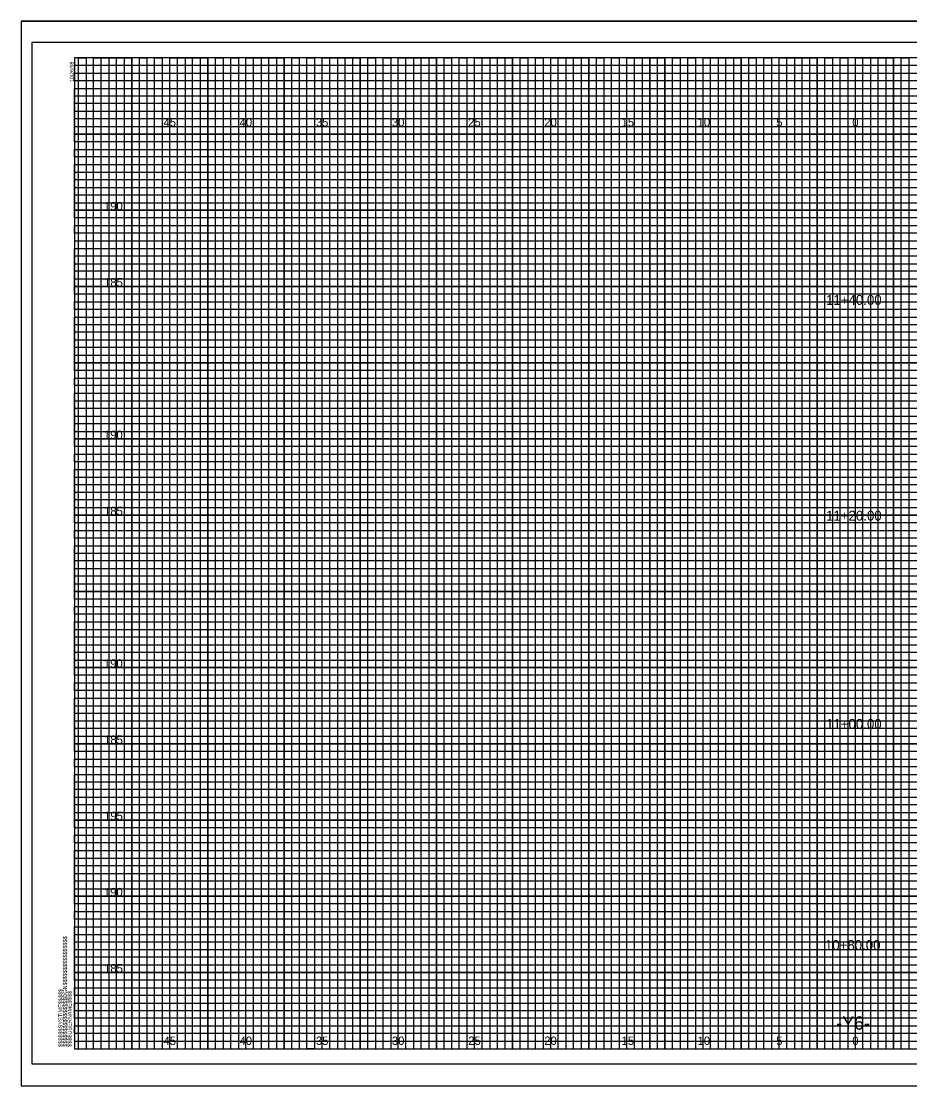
# Model space of a CAD drawing. Extents: x -4 to 103, y -2 to 138.
# Drawn here: x -3.5 to 54.8, y 68.4 to 138.2 of the extents above; entities that cross this region are included whole.
import ezdxf

# ---------------------------------------------------------------- set-up
doc = ezdxf.new("R2010")
doc.units = 0
for name, color, linetype in [('Old_Level_10', 7, 'Continuous'), ('Old_Level_16', 7, 'Continuous'), ('Old_Level_3', 7, 'Continuous'), ('Old_Level_4', 7, 'Continuous'), ('Old_Level_5', 7, 'Continuous'), ('Old_Level_8', 7, 'Continuous'), ('Prop Dimension', 7, 'Continuous'), ('Prop XS Dump Level', 7, 'Continuous'), ('Prop XS Finish Grade', 7, 'Continuous'), ('Prop XS SE Text', 7, 'Continuous'), ('Prop XS Subgrade Earthwork', 7, 'Continuous')]:
    doc.layers.add(name, color=color, linetype=linetype)

msp = doc.modelspace()

# ---------------------------------------------------------------- linework, layer by layer
at = {"layer": 'Old_Level_10'}
for p, q in [((1.25, 70.825), (1.25, 135.825)), ((3.75, 70.825), (3.75, 135.825)), ((6.25, 70.825), (6.25, 135.825)), ((8.75, 70.825), (8.75, 135.825)), ((11.25, 70.825), (11.25, 135.825)), ((13.75, 70.825), (13.75, 135.825)), ((16.25, 70.825), (16.25, 135.825)), ((18.75, 70.825), (18.75, 135.825)), ((21.25, 70.825), (21.25, 135.825)), ((23.75, 70.825), (23.75, 135.825)), ((26.25, 70.825), (26.25, 135.825)), ((28.75, 70.825), (28.75, 135.825)), ((31.25, 70.825), (31.25, 135.825)), ((33.75, 70.825), (33.75, 135.825)), ((36.25, 70.825), (36.25, 135.825)), ((38.75, 70.825), (38.75, 135.825)), ((41.25, 70.825), (41.25, 135.825)), ((43.75, 70.825), (43.75, 135.825)), ((46.25, 70.825), (46.25, 135.825)), ((48.75, 70.825), (48.75, 135.825)), ((51.25, 70.825), (51.25, 135.825)), ((53.75, 70.825), (53.75, 135.825)), ((0, 133.325), (74.25, 133.325)), ((0, 130.825), (102.5, 130.825)), ((0, 128.325), (102.5, 128.325)), ((0, 125.825), (102.5, 125.825)), ((0, 123.325), (102.5, 123.325)), ((0, 120.825), (102.5, 120.825)), ((0, 118.325), (102.5, 118.325)), ((0, 115.825), (102.5, 115.825)), ((0, 113.325), (102.5, 113.325)), ((0, 110.825), (102.5, 110.825)), ((0, 108.325), (102.5, 108.325)), ((0, 105.825), (102.5, 105.825)), ((0, 103.325), (102.5, 103.325)), ((0, 100.825), (102.5, 100.825)), ((0, 98.325), (102.5, 98.325)), ((0, 95.825), (102.5, 95.825)), ((0, 93.325), (102.5, 93.325)), ((0, 90.825), (102.5, 90.825)), ((0, 88.325), (102.5, 88.325)), ((0, 85.825), (102.5, 85.825)), ((0, 83.325), (102.5, 83.325)), ((0, 80.825), (102.5, 80.825)), ((0, 78.325), (102.5, 78.325)), ((0, 75.825), (102.5, 75.825)), ((0, 73.325), (102.5, 73.325))]:
    msp.add_line(p, q, dxfattribs=at)
at = {"layer": 'Old_Level_3'}
for p, q in [((-3.5, 138.225), (103.4, 138.225)), ((-3.5, 138.225), (-3.5, 68.4)), ((-3.5, 68.4), (102.1625, 68.4))]:
    msp.add_line(p, q, dxfattribs=at)
at = {"layer": 'Old_Level_4'}
msp.add_lwpolyline([(103, 136.825), (-2.8, 136.825), (-2.8, 69.825), (103, 69.825)], close=True, dxfattribs=at)
at = {"layer": 'Old_Level_5'}
msp.add_lwpolyline([(103.4, 138.225), (-3.5, 138.225), (-3.5, 68.4), (103.4, 68.4)], close=True, dxfattribs=at)
at = {"layer": 'Old_Level_8'}
for points in [[(1.25, 70.825), (1.25, 135.825), (3.75, 135.825), (3.75, 70.825), (6.25, 70.825), (6.25, 135.825), (8.75, 135.825), (8.75, 70.825), (11.25, 70.825), (11.25, 135.825), (13.75, 135.825), (13.75, 70.825), (16.25, 70.825), (16.25, 135.825), (18.75, 135.825), (18.75, 70.825), (21.25, 70.825), (21.25, 135.825), (23.75, 135.825), (23.75, 70.825), (26.25, 70.825), (26.25, 135.825), (28.75, 135.825), (28.75, 70.825), (31.25, 70.825), (31.25, 135.825), (33.75, 135.825), (33.75, 70.825), (36.25, 70.825), (36.25, 135.825), (38.75, 135.825), (38.75, 70.825), (41.25, 70.825), (41.25, 135.825), (43.75, 135.825), (43.75, 70.825), (46.25, 70.825), (46.25, 135.825), (48.75, 135.825), (48.75, 70.825), (51.25, 70.825), (51.25, 135.825), (53.75, 135.825), (53.75, 70.825)], [(102.5, 130.825), (0, 130.825), (0, 133.325), (74.25, 133.325)], [(102.5, 125.825), (0, 125.825), (0, 128.325), (102.5, 128.325)], [(102.5, 120.825), (0, 120.825), (0, 123.325), (102.5, 123.325)], [(102.5, 115.825), (0, 115.825), (0, 118.325), (102.5, 118.325)], [(102.5, 110.825), (0, 110.825), (0, 113.325), (102.5, 113.325)], [(102.5, 105.825), (0, 105.825), (0, 108.325), (102.5, 108.325)], [(102.5, 100.825), (0, 100.825), (0, 103.325), (102.5, 103.325)], [(102.5, 95.825), (0, 95.825), (0, 98.325), (102.5, 98.325)], [(102.5, 90.825), (0, 90.825), (0, 93.325), (102.5, 93.325)], [(102.5, 85.825), (0, 85.825), (0, 88.325), (102.5, 88.325)], [(102.5, 80.825), (0, 80.825), (0, 83.325), (102.5, 83.325)], [(102.5, 75.825), (0, 75.825), (0, 78.325), (102.5, 78.325)], [(0, 73.325), (102.5, 73.325)]]:
    msp.add_lwpolyline(points, dxfattribs=at)
at = {"layer": 'Prop Dimension'}
for points in [[(0.25, 70.825), (0.25, 135.825), (0.75, 135.825), (0.75, 70.825), (1.75, 70.825), (1.75, 135.825), (2.25, 135.825), (2.25, 70.825), (2.75, 70.825), (2.75, 135.825), (3.25, 135.825), (3.25, 70.825), (4.25, 70.825), (4.25, 135.825), (4.75, 135.825), (4.75, 70.825), (5.25, 70.825), (5.25, 135.825), (5.75, 135.825), (5.75, 70.825), (6.75, 70.825), (6.75, 135.825), (7.25, 135.825), (7.25, 70.825), (7.75, 70.825), (7.75, 135.825), (8.25, 135.825), (8.25, 70.825), (9.25, 70.825), (9.25, 135.825), (9.75, 135.825), (9.75, 70.825), (10.25, 70.825), (10.25, 135.825), (10.75, 135.825), (10.75, 70.825), (11.75, 70.825), (11.75, 135.825), (12.25, 135.825), (12.25, 70.825), (12.75, 70.825), (12.75, 135.825), (13.25, 135.825), (13.25, 70.825), (14.25, 70.825), (14.25, 135.825), (14.75, 135.825), (14.75, 70.825), (15.75, 70.825), (15.25, 70.825), (15.25, 135.825), (15.75, 135.825), (15.75, 70.825), (16.75, 70.825), (16.75, 135.825), (17.25, 135.825), (17.25, 70.825), (17.75, 70.825), (17.75, 135.825), (18.25, 135.825), (18.25, 70.825), (19.25, 70.825), (19.25, 135.825), (19.75, 135.825), (19.75, 70.825), (20.25, 70.825), (20.25, 135.825), (20.75, 135.825), (20.75, 70.825), (21.75, 70.825), (21.75, 135.825), (22.25, 135.825), (22.25, 70.825), (22.75, 70.825), (22.75, 135.825), (23.25, 135.825), (23.25, 70.825), (24.25, 70.825), (24.25, 135.825), (24.75, 135.825), (24.75, 70.825), (25.25, 70.825), (25.25, 135.825), (25.75, 135.825), (25.75, 70.825), (26.75, 70.825), (26.75, 135.825), (27.25, 135.825), (27.25, 70.825), (27.75, 70.825), (27.75, 135.825), (28.25, 135.825), (28.25, 70.825), (29.25, 70.825), (29.25, 135.825), (29.75, 135.825), (29.75, 70.825), (30.25, 70.825), (30.25, 135.825), (30.75, 135.825), (30.75, 70.825)], [(30.75, 70.825), (31.75, 70.825), (31.75, 135.825), (32.25, 135.825), (32.25, 70.825), (32.75, 70.825), (32.75, 135.825), (33.25, 135.825), (33.25, 70.825), (34.25, 70.825), (34.25, 135.825), (34.75, 135.825), (34.75, 70.825), (35.25, 70.825), (35.25, 135.825), (35.75, 135.825), (35.75, 70.825), (36.75, 70.825), (36.75, 135.825), (37.25, 135.825), (37.25, 70.825), (37.75, 70.825), (37.75, 135.825), (37.75, 70.825)], [(38.25, 135.825), (38.25, 70.825), (39.25, 70.825), (39.25, 135.825), (39.75, 135.825), (39.75, 70.825), (40.25, 70.825), (40.25, 135.825), (40.75, 135.825), (40.75, 70.825), (41.75, 70.825), (41.75, 135.825), (42.25, 135.825), (42.25, 70.825), (42.75, 70.825), (42.75, 135.825), (43.25, 135.825), (43.25, 70.825), (43.75, 70.825), (44.25, 70.825), (44.25, 135.825), (44.75, 135.825), (44.75, 70.825), (45.25, 70.825), (45.25, 135.825), (45.75, 135.825), (45.75, 70.825), (46.75, 70.825), (46.75, 135.825), (47.25, 135.825), (47.25, 70.825), (47.75, 70.825), (47.75, 135.825), (48.25, 135.825), (48.25, 70.825), (49.25, 70.825), (49.25, 135.825), (49.75, 135.825), (49.75, 70.825), (50.25, 70.825), (50.25, 135.825), (50.75, 135.825), (50.75, 70.825), (51.75, 70.825), (51.75, 135.825), (52.25, 135.825), (52.25, 70.825), (52.75, 70.825), (52.75, 135.825), (53.25, 135.825), (53.25, 70.825), (54.25, 70.825), (54.25, 135.825), (54.75, 135.825), (54.75, 70.825), (55.25, 70.825)], [(0, 132.825), (0, 133.825), (74.25, 133.825), (74.25, 134.325), (0, 134.325), (0, 134.825), (74.25, 134.825), (74.25, 135.325), (0, 135.325)], [(102.5, 132.825), (0, 132.825)], [(102.5, 131.825), (0, 131.825), (0, 132.325), (102.5, 132.325)], [(102.5, 130.325), (0, 130.325), (0, 131.325), (102.5, 131.325)], [(102.5, 129.325), (0, 129.325), (0, 129.825), (102.5, 129.825)], [(102.5, 127.825), (0, 127.825), (0, 128.825), (102.5, 128.825)], [(102.5, 126.825), (0, 126.825), (0, 127.325), (102.5, 127.325)], [(102.5, 125.325), (0, 125.325), (0, 126.325), (102.5, 126.325)], [(102.5, 124.325), (0, 124.325), (0, 124.825), (102.5, 124.825)], [(0, 123.825), (102.5, 123.825)], [(102.5, 122.825), (0, 122.825)], [(102.5, 121.825), (0, 121.825), (0, 122.325), (102.5, 122.325)], [(102.5, 120.325), (0, 120.325), (0, 121.325), (102.5, 121.325)], [(102.5, 119.325), (0, 119.325), (0, 119.825), (102.5, 119.825)], [(102.5, 117.825), (0, 117.825), (0, 118.825), (102.5, 118.825)], [(102.5, 116.825), (0, 116.825), (0, 117.325), (102.5, 117.325)], [(102.5, 115.325), (0, 115.325), (0, 116.325), (102.5, 116.325)], [(102.5, 114.325), (0, 114.325), (0, 114.825), (102.5, 114.825)], [(102.5, 112.825), (0, 112.825), (0, 113.825), (102.5, 113.825)], [(102.5, 111.825), (0, 111.825), (0, 112.325), (102.5, 112.325)], [(102.5, 110.325), (0, 110.325), (0, 111.325), (102.5, 111.325)], [(102.5, 109.325), (0, 109.325), (0, 109.825), (102.5, 109.825)], [(102.5, 107.825), (0, 107.825), (0, 108.825), (102.5, 108.825)], [(102.5, 106.825), (0, 106.825), (0, 107.325), (102.5, 107.325)], [(102.5, 105.325), (0, 105.325), (0, 106.325), (102.5, 106.325)], [(102.5, 104.325), (0, 104.325), (0, 104.825), (102.5, 104.825)], [(102.5, 102.825), (0, 102.825), (0, 103.825), (102.5, 103.825)], [(102.5, 101.825), (0, 101.825), (0, 102.325)], [(0, 102.325), (102.5, 102.325)], [(102.5, 100.325), (0, 100.325), (0, 101.325), (102.5, 101.325)], [(102.5, 99.325), (0, 99.325), (0, 99.825), (102.5, 99.825)], [(102.5, 97.825), (0, 97.825), (0, 98.825), (102.5, 98.825)], [(102.5, 96.825), (0, 96.825), (0, 97.325), (102.5, 97.325)], [(102.5, 95.325), (0, 95.325), (0, 96.325), (102.5, 96.325)], [(102.5, 94.325), (0, 94.325), (0, 94.825), (102.5, 94.825)], [(102.5, 92.825), (0, 92.825), (0, 93.825), (102.5, 93.825)], [(102.5, 91.825), (0, 91.825), (0, 92.325), (102.5, 92.325)], [(102.5, 90.325), (0, 90.325), (0, 91.325), (102.5, 91.325)], [(102.5, 89.325), (0, 89.325), (0, 89.825), (102.5, 89.825)], [(102.5, 87.825), (0, 87.825), (0, 88.825), (102.5, 88.825)], [(102.5, 86.825), (0, 86.825), (0, 87.325), (102.5, 87.325)], [(102.5, 85.325), (0, 85.325), (0, 86.325), (102.5, 86.325)], [(102.5, 84.325), (0, 84.325), (0, 84.825), (102.5, 84.825)], [(102.5, 82.825), (0, 82.825), (0, 83.825), (102.5, 83.825)], [(102.5, 81.825), (0, 81.825), (0, 82.325), (102.5, 82.325)], [(102.5, 80.325), (0, 80.325), (0, 81.325), (102.5, 81.325)], [(102.5, 79.325), (0, 79.325), (0, 79.825), (102.5, 79.825)], [(102.5, 77.825), (0, 77.825), (0, 78.825), (102.5, 78.825)], [(102.5, 76.825), (0, 76.825), (0, 77.325), (102.5, 77.325)], [(102.5, 75.325), (0, 75.325), (0, 76.325), (102.5, 76.325)], [(102.5, 74.325), (0, 74.325), (0, 74.825), (102.5, 74.825)], [(102.5, 72.825), (0, 72.825), (0, 73.825), (102.5, 73.825)], [(102.5, 71.825), (0, 71.825), (0, 72.325), (102.5, 72.325)], [(0, 71.325), (102.5, 71.325)]]:
    msp.add_lwpolyline(points, dxfattribs=at)
at = {"layer": 'Prop XS SE Text'}
for p, q in [((0, 70.825), (0, 70.825)), ((0, 70.825), (0, 70.825)), ((-3.5, 68.4), (103.4, 68.4))]:
    msp.add_line(p, q, dxfattribs=at)
msp.add_lwpolyline([(102.5, 135.825), (0, 135.825), (0, 70.825), (102.5, 70.825)], close=True, dxfattribs=at)

# ---------------------------------------------------------------- texts
at = {"layer": 'Old_Level_16'}
for s, p in [('45', (5.8399, 131.325)), ('40', (10.8313, 131.325)), ('35', (15.8399, 131.325)), ('30', (20.8313, 131.325)), ('25', (25.8399, 131.325)), ('20', (30.8313, 131.325)), ('15', (35.9058, 131.325)), ('10', (40.8971, 131.325)), ('5', (46.0574, 131.325)), ('0', (51.0488, 131.325)), ('0', (51.0488, 131.325)), ('45', (5.8399, 71.075)), ('40', (10.8313, 71.075)), ('35', (15.8399, 71.075)), ('30', (20.8313, 71.075)), ('25', (25.8399, 71.075)), ('20', (30.8313, 71.075)), ('15', (35.9058, 71.075)), ('10', (40.8971, 71.075)), ('5', (46.0574, 71.075)), ('0', (51.0488, 71.075)), ('0', (51.0488, 71.075))]:
    msp.add_text(s, height=0.55, dxfattribs=at).set_placement(p)
at = {"layer": 'Old_Level_8'}
msp.add_text('040397', height=0.0025, rotation=90, dxfattribs=at).set_placement((-0.0007, 135.8114))
at = {"layer": 'Prop XS Dump Level'}
msp.add_text('-Y6-', height=0.875, dxfattribs=at).set_placement((49.9985, 72.075))
at = {"layer": 'Prop XS Finish Grade'}
for s, p in [('190', (1.9296, 125.825)), ('185', (1.9383, 120.825)), ('190', (1.9296, 110.825)), ('185', (1.9383, 105.825)), ('190', (1.9296, 95.825)), ('185', (1.9383, 90.825)), ('195', (1.9383, 85.825)), ('190', (1.9296, 80.825)), ('185', (1.9383, 75.825))]:
    msp.add_text(s, height=0.55, dxfattribs=at).set_placement(p)
at = {"layer": 'Prop XS SE Text'}
for s, height, p in [('10/26/98', 0.25, (-0.0625, 134.2345)), ('$$$$$$$$$$$$$$$$DGN$$$$$$$$$$$$$$$$', 0.2625, (-0.5, 70.95)), ('$$$$$$SYSTIME$$$$$', 0.2625, (-0.7973, 70.9497)), ('$$$$USERNAME$$$$', 0.2625, (-0.2, 70.95))]:
    msp.add_text(s, height=height, rotation=90, dxfattribs=at).set_placement(p)
at = {"layer": 'Prop XS Subgrade Earthwork'}
for s, p in [('11+40.00', (49.3286, 119.6222)), ('11+20.00', (49.3286, 105.4705)), ('11+00.00', (49.3286, 91.8087)), ('10+80.00', (49.2508, 77.3029))]:
    msp.add_text(s, height=0.65, dxfattribs=at).set_placement(p)

doc.saveas('drawing.dxf')
